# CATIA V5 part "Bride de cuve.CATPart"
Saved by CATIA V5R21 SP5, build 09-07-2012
Part number: Bride de cuve
Bounding box of the stored display mesh (mm): x -2589.279 to 2589.279, y -2586.606 to 2586.606, z 0 to 1050
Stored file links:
  \\etu.ad.univ-lorraine.fr\bordron1\Documents\Parts EPR\Bride de cuve.CATPart
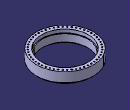
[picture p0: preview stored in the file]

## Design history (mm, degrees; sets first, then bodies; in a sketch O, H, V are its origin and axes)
AxisSystem1: origin (0, 0, 0), X (1, 0, 0), Y (0, 1, 0), Z (0, 0, 1)
Body1 (main body)
  Sketch1 on YZ plane of AxisSystem1, origin (0, 0, 0), H (0, 1, 0), V (0, 0, 1)
    line L1 (-2422, 0) -> (-2140, 0)
    point P2 (-2140, 0)
    reference intersected line E1 through (0, 0) direction (0, 1) from ZX plane of AxisSystem1
    line L2 (-2590, 168) -> (-2590, 1050)
    point P3 (-2590, 168)
    line L3 (-2590, 1050) -> (-2140, 1050)
    line L4 (-2140, 1050) -> (-2140, 750)
    line L5 (-2140, 750) -> (-2065, 750)
    line L6 (-2065, 750) -> (-2065, 75)
    reference intersected line E2 through (0, 0) direction (-1, 0) from XY plane of AxisSystem1
    line L7 (-2140, 0) -> (-2065, 75)
    arc A1 centre (-2590, 0) radius 168 from (-2422, 0) to (-2590, 168) ccw
    point P9 (-2590, 0)
    point P10 (-2590, 168)
    distance P2 E1 = 2140
    length L4 = 300
    length L5 = 75
    distance L6 L2 = 525
    distance L1 L3 = 1050
    distance L6 P2 = 75
    angle L7 L1 = 45
    length L1 = 282
    horizontal: L1 H, L3 H, L5 H
    vertical: L2 V, L4 V, L6 V
    coincidence: L1 E2, P9 L2, P9 H, P10 L2, P3 P10
  Shaft1: profile Sketch1, axis edge [ZX plane of AxisSystem1 | YZ plane of AxisSystem1], angle 360
  Sketch2 on XY plane of AxisSystem1, origin (0, 0, 0), H (1, 0, 0), V (0, 1, 0)
    circle A1 centre (0, 2402) radius 60
    point P1 (0, 2402)
    radius A1 = 60
    distance P1 O = 2402
    coincidence: P1 V
  Pocket1: profile Sketch2, direction (0, 0, -1), length -600, opposite side through (limit type 6)
  CircPattern1: of Pocket1, instances 52, angular step 6.923, axis from edge [ZX plane of AxisSystem1 | YZ plane of AxisSystem1]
